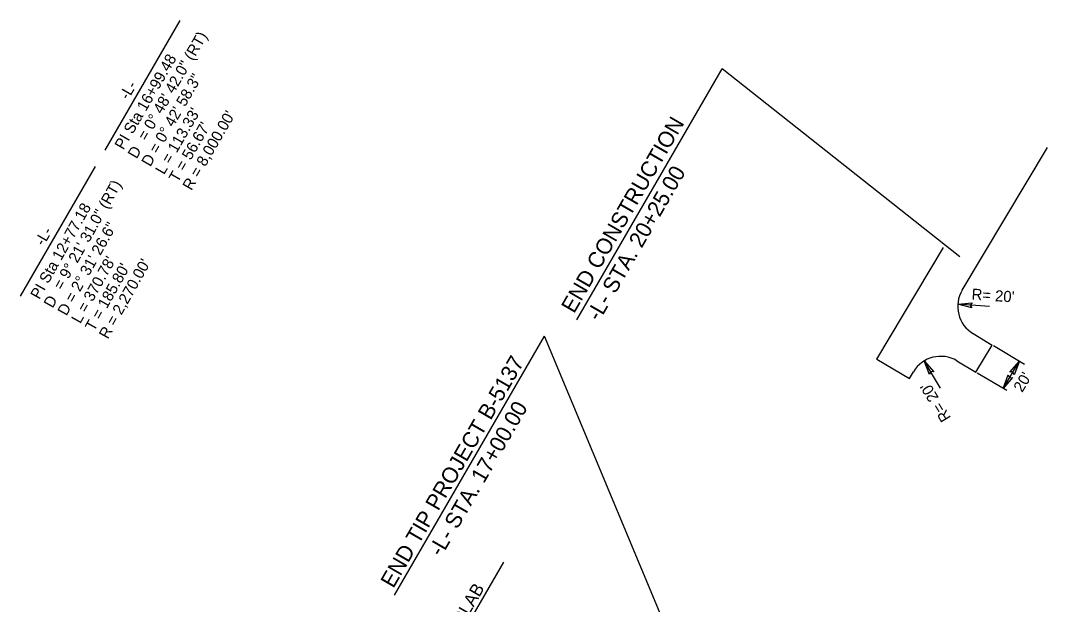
# Model space of a CAD drawing. Extents: x 1653308 to 1654073, y 597542 to 598622.
# Drawn here: x 1653424 to 1654073, y 598253 to 598622 of the extents above; entities that cross this region are included whole.
import ezdxf

# ---------------------------------------------------------------- set-up
doc = ezdxf.new("R2010")
doc.units = 0
for name, color, linetype in [('Prop Dimension', 7, 'Continuous'), ('Prop Dimension Text', 7, 'Continuous'), ('Prop EOT', 7, 'Continuous'), ('Prop Horizontal Alignment Curve and Spiral Data', 7, 'Continuous'), ('Prop Terminator CELL', 7, 'Continuous')]:
    doc.layers.add(name, color=color, linetype=linetype)

msp = doc.modelspace()

# ---------------------------------------------------------------- linework, layer by layer
at = {"layer": 'Prop Dimension'}
for p, q in [((1653775.5, 598433.14), (1653867.25, 598591.59)), ((1654017.43, 598472.87), (1653867.25, 598591.59)), ((1654036.04, 598441.63), (1654016.08, 598443)), ((1653660.38, 598259.38), (1653755.08, 598422.92)), ((1653850.86, 598193.8), (1653755.08, 598422.92)), ((1654058.24, 598405.06), (1654038.65, 598416.77)), ((1654005.25, 598390.13), (1653994.83, 598407.2)), ((1654044.7, 598389.86), (1654054.96, 598407.02)), ((1654047.02, 598388.47), (1654028.39, 598399.6)), ((1653657.71, 598156.32), (1653729.38, 598280.07))]:
    msp.add_line(p, q, dxfattribs=at)
at = {"layer": 'Prop EOT'}
for p, q in [((1654018.87, 598451.89), (1654072.71, 598541.97)), ((1653964.92, 598408.41), (1654007.02, 598478.86)), ((1654025.77, 598424.47), (1654037.79, 598417.28)), ((1653964.92, 598408.41), (1653967.49, 598412.71)), ((1654027.53, 598400.12), (1654037.79, 598417.28)), ((1653964.92, 598408.41), (1653985.52, 598396.1)), ((1654015.51, 598407.3), (1654027.53, 598400.12)), ((1653985.52, 598396.1), (1653988.09, 598400.39))]:
    msp.add_line(p, q, dxfattribs=at)
for centre, start, end in [((1654036.04, 598441.63), 149.13342, 239.13342), ((1654005.25, 598390.13), 59.13342, 149.13342)]:
    msp.add_arc(centre, 20, start, end, dxfattribs=at)
at = {"layer": 'Prop Horizontal Alignment Curve and Spiral Data'}
for p, q in [((1653477.66, 598540.34), (1653525.03, 598622.15)), ((1653424.28, 598448.15), (1653471.65, 598529.96))]:
    msp.add_line(p, q, dxfattribs=at)
at = {"layer": 'Prop Terminator CELL'}
for points in [[(1654024.96, 598440.84), (1654016.08, 598443), (1654025.22, 598443.98), (1654023.96, 598442.46)], [(1653998.2, 598398.71), (1653994.83, 598407.2), (1654000.91, 598400.31), (1653998.95, 598400.46)], [(1654049.01, 598400.09), (1654054.96, 598407.02), (1654051.69, 598398.43), (1654050.91, 598400.24)], [(1654050.65, 598396.79), (1654044.7, 598389.86), (1654047.97, 598398.45), (1654048.75, 598396.64)]]:
    msp.add_lwpolyline(points, close=True, dxfattribs=at)

# ---------------------------------------------------------------- texts
at = {"layer": 'Prop Dimension Text'}
for s, height, rotation, p in [('END CONSTRUCTION', 10, 59.92548, (1653773.77, 598436.7)), ('-L- STA. 20+25.00', 10, 59.92548, (1653789.65, 598431.69)), ("R= 20'", 7, 356.08261, (1654024.63, 598445.98)), ('END TIP PROJECT B-5137', 10, 59.92548, (1653659.68, 598263.2)), ("20'", 7, 59.13342, (1654056.77, 598386.93)), ("R= 20'", 7, 121.40888, (1654012, 598371.36)), ('-L- STA. 17+00.00', 10, 59.92548, (1653689.96, 598283.07)), ('END APPROACH SLAB', 8, 59.92548, (1653659.4, 598163.5))]:
    msp.add_text(s, height=height, rotation=rotation, dxfattribs=at).set_placement(p)
at = {"layer": 'Prop Horizontal Alignment Curve and Spiral Data'}
for s, rotation, p in [('= 0%%d 48\' 42.0" (RT)', 59.91351, (1653503.76, 598545.71)), ('PI Sta 16+99.48', 59.91351, (1653489.26, 598540.04)), ('D = 0%%d 42\' 58.3"', 59.91351, (1653506.22, 598529.43)), ('-L-', 59.92548, (1653492.23, 598571.56)), ("L = 113.33'", 59.91351, (1653514.88, 598524.41)), ("R = 8,000.00'", 59.91351, (1653532.18, 598514.39)), ("T = 56.67'", 59.91351, (1653523.53, 598519.4)), ('D', 59.91351, (1653497.57, 598534.44)), ('= 9%%d 21\' 31.0" (RT)', 60.74006, (1653450.57, 598451.49)), ('PI Sta 12+77.18', 60.74006, (1653436.15, 598445.61)), ('-L-', 59.92548, (1653438.84, 598479.37)), ('D = 2%%d 31\' 26.6"', 60.74006, (1653453.27, 598435.25)), ("L = 370.78'", 60.74006, (1653461.99, 598430.36)), ("R = 2,270.00'", 60.74006, (1653479.44, 598420.58)), ("T = 185.80'", 60.74006, (1653470.72, 598425.47)), ('D', 60.74006, (1653444.55, 598440.13))]:
    msp.add_text(s, height=7, rotation=rotation, dxfattribs=at).set_placement(p)

doc.saveas('drawing.dxf')
